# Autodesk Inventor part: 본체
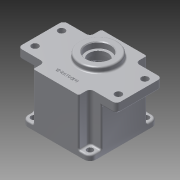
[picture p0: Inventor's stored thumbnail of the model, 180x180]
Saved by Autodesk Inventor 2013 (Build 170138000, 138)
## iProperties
Created: 2015-07
Part Number: 본체
Material: 알루미늄 6061
Document SubType Name: Modeling
Designer: user
Density: 2.71 g/cm^3
Mass: 705.341 g
Surface Area: 672.954 cm^2
Volume: 260.273 cm^3
Author: user
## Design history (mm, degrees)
sketch "스케치1"
  geometry: L1 (-30, 45)-(30, 45); L2 (30, 45)-(30, -45); L3 (30, -45)-(-30, -45); L4 (-30, -45)-(-30, 45); 3 further points
  constraints: 8 end point, 2 midpoint, 2 parallel, 1 horizontal, 1 horizontal alignment, 1 perpendicular, 1 vertical alignment
  dimensions: "d0" = 90 distance of L3.end L1.start; "d2" = 60 distance of L1.start L1.end
extrude "돌출1" new body sketch "스케치1" stored distance "d3" = 58; taper "d4" = 0 deg
sketch "스케치2"
  geometry: L1 (30, 45)-(-30, 45) reference; L2 (-30, 45)-(-30, -45) reference; L3 (-30, -45)-(30, -45) reference; L4 (30, -45)-(30, 45) reference; L5 (-65, 30)-(65, 30); L6 (65, 30)-(65, -30); L7 (65, -30)-(-65, -30); L8 (-65, -30)-(-65, 30); 3 further points
  constraints: 8 end point, 2 midpoint, 2 parallel, 1 horizontal, 1 horizontal alignment, 1 perpendicular, 1 vertical alignment
  dimensions: "d5" = 130 distance of L5.start L5.end; "d7" = 60 distance of L5.end L6.end
extrude "돌출2" join sketch "스케치2" distance "d8" = 12; taper "d9" = 0 deg
sketch "스케치3"
  geometry: L1 (30, -29)-(-30, -29) reference; L2 (-30, -29)-(-30, 29) reference; L3 (-30, 29)-(-65, 29) reference; L4 (-65, 29)-(-65, 41) reference; L5 (-65, 41)-(65, 41) reference; L6 (65, 41)-(65, 29) reference; L7 (65, 29)-(30, 29) reference; L8 (30, 29)-(30, -29) reference; L9 (0, -29)-(-45, -29); L10 (-45, -29)-(-45, 32.5); L11 (-45, 32.5)-(0, 32.5); L12 (0, 32.5)-(0, -29); L13 (45, 32.5)-(0, 32.5); L14 (45, -29)-(45, 32.5); L15 (0, -29)-(45, -29); 1 further point
  constraints: 14 end point, 2 perpendicular, 2 symmetric about line, 1 midpoint, 1 parallel
  dimensions: "d10" = 45 distance of L9.start L9.end; "d11" = 45 distance of L10.end L11.end; "d12" = 3.5 distance between parallel lines of L11 L3
extrude "돌출3" join sketch "스케치3" stored distance "d13" = 60; taper "d14" = 0 deg
sketch "스케치4"
  geometry: L1 (-30, -30)-(-30, -45) reference; L2 (-30, -45)-(30, -45) reference; L3 (30, -45)-(30, -30) reference; L4 (45, -30)-(30, -30) reference; L5 (45, -30)-(45, 30) reference; L6 (30, 30)-(45, 30) reference; L7 (30, 30)-(30, 45) reference; L8 (30, 45)-(-30, 45) reference; L9 (-30, 45)-(-30, 30) reference; L10 (-45, 30)-(-30, 30) reference; L11 (-45, -30)-(-45, 30) reference; L12 (-30, -30)-(-45, -30) reference; L13 (-45, 45)-(45, 45); L14 (45, 45)-(45, -45); L15 (45, -45)-(-45, -45); L16 (-45, -45)-(-45, 45); 3 further points
  constraints: 8 end point, 2 midpoint, 2 parallel, 1 horizontal, 1 horizontal alignment, 1 perpendicular, 1 vertical alignment
  dimensions: "d15" = 90 distance of L13.start L13.end; "d17" = 90 distance of L15.end L13.start
extrude "돌출4" join sketch "스케치4" distance "d18" = 7; taper "d19" = 0 deg
sketch "스케치8"
  geometry: C1 r 39 at (0, 0); 1 further point
  constraints: 1 centre point, 1 coincident
  dimensions: "d20" = 78 diameter of C1
extrude "돌출5" cut sketch "스케치8" distance "d21" = 61; taper "d22" = 0 deg
sketch "스케치9"
  geometry: C1 r 39 at (0, 0) reference; C2 r 40 at (0, 0)
  constraints: 1 centre point, 1 coincident
  dimensions: "d23" = 80 diameter of C2
extrude "돌출6" cut sketch "스케치9" distance "d24" = 9; taper "d25" = 0 deg
sketch "스케치10"
  geometry: L1 (30, -45)-(30, -30) reference; L2 (0, 0)-(55, 0); L3 (55, 17.5)-(55, -17.5); 2 further points
  constraints: 4 end point, 2 coincident, 2 perpendicular, 1 midpoint
  dimensions: "d26" = 55 distance of L2.end L2.start; "d28" = 35 distance of L3.start L3.end
hole "구멍1" sketch "스케치10" at (55, 17.5), (55, -17.5) diameter "d29" = 9; stored, may be unused: countersink angle "d33" = 90 deg, drill point angle "d35" = 118 deg; dims "d30" = 6, "d31" = 4, "d32" = 2, "d34" = 12
fillet "모깎기1" dims "d36" = 2
fillet "모깎기2" dims "d37" = 2
fillet "모깎기3" dims "d38" = 2
fillet "모깎기4" dims "d39" = 8
fillet "모깎기5" dims "d40" = 5
sketch "스케치11"
  geometry: L1 (-32, 43)-(-32, 35) reference; L2 (-37, 43)-(-32, 43) reference; L3 (-43, 32)-(-43, 37) reference; L4 (-35, 32)-(-43, 32) reference; L5 (-43, -32)-(-35, -32) reference; L6 (-43, -37)-(-43, -32) reference; L7 (-32, -43)-(-37, -43) reference; L8 (-32, -35)-(-32, -43) reference; L9 (32, -43)-(32, -35) reference; L10 (37, -43)-(32, -43) reference; L11 (43, -32)-(43, -37) reference; L12 (35, -32)-(43, -32) reference; A1 r 6 centre (37, 37) between (43, 37) and (37, 43) reference; A2 r 3 centre (-35, 35) between (-35, 32) and (-32, 35) reference; A3 r 6 centre (-37, 37) between (-37, 43) and (-43, 37) reference; A4 r 3 centre (-35, -35) between (-32, -35) and (-35, -32) reference; A5 r 6 centre (-37, -37) between (-43, -37) and (-37, -43) reference; A6 r 3 centre (35, -35) between (35, -32) and (32, -35) reference; A7 r 6 centre (37, -37) between (37, -43) and (43, -37) reference; 5 further points
  constraints: 4 coincident
hole "구멍2" sketch "스케치11" at (-37, 37), (-37, -37), (37, -37), (37, 37) diameter "d41" = 8; stored, may be unused: countersink angle "d45" = 90 deg, drill point angle "d47" = 118 deg; dims "d42" = 6, "d43" = 4, "d44" = 2, "d46" = 20
sketch "스케치12"
  geometry: L1 (-40, -29)-(-45, -29) reference; L2 (-45, -29)-(-45, 41) reference; L3 (-45, 41)-(45, 41) reference; L4 (45, 41)-(45, -29) reference; L5 (45, -29)-(40, -29) reference; L6 (40, -29)-(40, -20) reference; L7 (40, -20)-(39, -20) reference; L8 (39, -20)-(39, 32) reference; L9 (39, 32)-(-39, 32) reference; L10 (-39, 32)-(-39, -20) reference; L11 (-39, -20)-(-40, -20) reference; L12 (-40, -20)-(-40, -29) reference; L13 (0, 0)-(0, 48); L14 (36, 41)-(36, 48); L15 (11, 0)-(11, 67); L16 (31.5, 25)-(31.5, 41); L17 (11, 48)-(36, 48); L18 (11, 25)-(31.5, 25); L19 (36, 41)-(31.5, 41)
  constraints: 14 end point, 5 parallel, 4 point on line, 2 perpendicular, 1 collinear
  dimensions: "d48" = 11 distance between parallel lines of L13 L15; "d52" = 7 distance between parallel lines of L3 L17; "d53" = 7 distance between parallel lines of L9 L18; "d54" = 50 diameter of L14 L15; "d55" = 41 diameter of L16 L15
revolve "회전1" sketch "스케치12" stored, may be unused: angle "d56" = 90 deg
sketch "스케치13"
  geometry: L1 (0, 0)-(0, 53.036); L2 (-20, 0)-(-20, 53.036); L3 (-40, -29)-(-45, -29) reference; L4 (-45, -29)-(-45, 41) reference; L5 (-45, 41)-(-14, 41) reference; L6 (-14, 41)-(-14, 48) reference; L7 (-14, 48)-(36, 48) reference; L8 (36, 48)-(36, 41) reference; L9 (36, 41)-(45, 41) reference; L10 (45, 41)-(45, -29) reference; L11 (45, -29)-(40, -29) reference; L12 (40, -29)-(40, -20) reference; L13 (40, -20)-(39, -20) reference; L14 (39, -20)-(39, 32) reference; L15 (39, 32)-(31.5, 32) reference; L16 (31.5, 32)-(31.5, 25) reference; L17 (31.5, 25)-(-9.5, 25) reference; L18 (-9.5, 25)-(-9.5, 32) reference; L19 (-9.5, 32)-(-39, 32) reference; L20 (-39, 32)-(-39, -20) reference; L21 (-39, -20)-(-40, -20) reference; L22 (-40, -20)-(-40, -29) reference; L23 (-34, 32)-(-20, 32); L24 (-9.5, 25)-(6, 25); L25 (-34, 25)-(-20, 25); L26 (-34, 32)-(-34, 25)
  constraints: 13 end point, 3 collinear, 2 point on line, 1 parallel, 1 perpendicular, 1 vertical
  dimensions: "d57" = 20 distance between parallel lines of L2 L1; "d61" = 0 distance between parallel lines of L23 L19; "d62" = 7 distance between parallel lines of L25 L19; "d63" = 28 diameter of L26 L2; "d64" = 21.03581 distance from line of L2.end L19; "d65" = 32 distance from line of L2.start L19
revolve "회전2" sketch "스케치13" stored, may be unused: angle "d66" = 90 deg
fillet "모깎기6" dims "d67" = 2
fillet "모깎기8" dims "d69" = 3
sketch "스케치14"
  geometry: A1 r 14 centre (0, -31) between (-10.493, -21.732) and (10.493, -21.732) reference; 1 further point
hole "구멍3" sketch "스케치14" at (0, -31) diameter "d70" = 19; stored, may be unused: countersink angle "d74" = 90 deg, drill point angle "d76" = 0 deg; dims "d71" = 6, "d72" = 22, "d73" = 7, "d75" = 8
fillet "모깎기9" dims "d77" = 2
fillet "모깎기10" dims "d78" = 0.3
chamfer "모따기1" distance "d79" = 1; stored, may be unused: second distance "d80" = 2, angle "d81" = 45 deg
sketch "스케치15"
  geometry: A1 r 20.5 centre (0, 0) between (11.115, -17.225) and (-11.115, -17.225) reference; 1 further point
hole "구멍4" sketch "스케치15" at (0, 0) diameter "d82" = 25; stored, may be unused: countersink angle "d86" = 90 deg, drill point angle "d88" = 0 deg; dims "d83" = 6, "d84" = 35, "d85" = 10, "d87" = 15
sketch "스케치16"
  geometry: C1 r 25 at (0, 0) reference; 1 further point
hole "구멍5" sketch "스케치16" at (0, 0) diameter "d89" = 25; stored, may be unused: countersink angle "d93" = 90 deg, drill point angle "d95" = 0 deg; dims "d90" = 6, "d91" = 32, "d92" = 8, "d94" = 13
fillet "모깎기11" dims "d96" = 0.3
chamfer "모따기2" distance "d97" = 1; stored, may be unused: second distance "d98" = 2, angle "d99" = 45 deg
sketch "스케치20"
  geometry: L1 (0, 0)-(24.749, 24.749); L2 (0, 0)-(35, 0); A1 r 39 centre (0, 0) between (32.777, 21.134) and (21.134, 32.777) reference; A2 r 4 centre (24.749, 24.749) between (21.809, 27.462) and (27.462, 21.809); A3 r 3.5 centre (29.836, 19.238) between (32.777, 21.134) and (27.412, 21.762); A4 r 3.5 centre (19.238, 29.836) between (21.762, 27.412) and (21.134, 32.777)
  constraints: 10 point on circle, 4 end point, 4 tangent, 3 centre point, 2 coincident, 1 equal length, 1 horizontal
  dimensions: "d112" = 35 distance of L1.start L1.end; "d113" = 45 deg angle of L2 L1; "d115" = 8 diameter of A2; "d116" = 7 diameter of A3; "d117" = 7 diameter of A4
extrude "돌출8" join sketch "스케치20" distance "d118" = 52; taper "d119" = 0 deg
fillet "모깎기12" dims "d123" = 2
fillet "모깎기13" dims "d124" = 2
fillet "모깎기14" dims "d125" = 2
sketch "스케치21"
  geometry: A1 r 4 centre (24.749, 24.749) between (21.809, 27.462) and (27.462, 21.809) reference; A2 r 4 centre (24.749, -24.749) between (27.462, -21.809) and (21.809, -27.462) reference; A3 r 4 centre (-24.749, -24.749) between (-21.809, -27.462) and (-27.462, -21.809) reference; A4 r 4 centre (-24.749, 24.749) between (-27.462, 21.809) and (-21.809, 27.462) reference
hole "구멍6" sketch "스케치21" at (-24.749, 24.749), (-24.749, -24.749), (24.749, -24.749), (24.749, 24.749) diameter "d126" = 3.459; stored, may be unused: countersink angle "d130" = 90 deg, drill point angle "d132" = 118 deg; dims "d127" = 12, "d128" = 32, "d129" = 8, "d131" = 15
sketch "스케치22"
  geometry: L1 (-28, -45)-(28, -45) reference; L2 (-65, 25)-(-65, -25) reference; L3 (0, -45)-(0, -30); 2 further points
  constraints: 2 end point, 1 coincident, 1 midpoint, 1 parallel, 1 other
  dimensions: "d133" = 15 distance of L3.start L3.end
feature "엠보싱1" sketch "스케치22" dims "d134" = 0.5, "d135" = 0
node "솔리드1"
mirror "대칭1"
pattern_circular "원형 패턴2" dims angle "d121" = 360 deg
node "투영된 루프1"
node "투영된 루프2"
node "투영된 루프3"
node "절단 모서리 투영1"
node "절단 모서리 투영3"
node "절단 모서리 투영4"
other parameters: "d59" = 28, "d60" = 7, "d105" = 7
